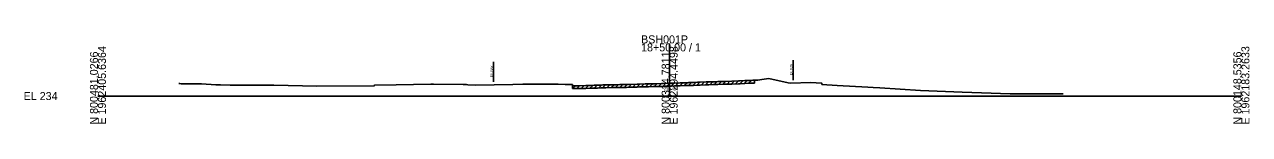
# Model space of a CAD drawing. Extents: x -26 to 1403, y -10 to 19587.
# Drawn here: x -25.7 to 402.8, y 2490.3 to 2521.3 of the extents above; entities that cross this region are included whole.
import ezdxf

# ---------------------------------------------------------------- set-up
doc = ezdxf.new("R2010")
doc.units = 0
for name, color, linetype in [('Default', 7, 'Continuous'), ('RD_GPK_XS_Cell', 7, 'Continuous'), ('RD_XS_ExGround', 7, 'Continuous'), ('RD_XS_ExPaveRet', 7, 'Continuous'), ('RD_XS_ExRW', 7, 'Continuous'), ('RD_XS_TX_Elev_EX', 7, 'Continuous')]:
    doc.layers.add(name, color=color, linetype=linetype)

msp = doc.modelspace()

# ---------------------------------------------------------------- linework, layer by layer
at = {"layer": 'RD_GPK_XS_Cell'}
for p, q in [((200, 2500), (200, 2518.45)), ((0, 2500), (200, 2500)), ((200, 2500), (400, 2500))]:
    msp.add_line(p, q, dxfattribs=at)
at = {"layer": 'RD_XS_ExGround'}
msp.add_lwpolyline([(28.28, 2504.42), (28.6, 2504.39), (29.16, 2504.33), (31.63, 2504.31), (35.81, 2504.27), (36.26, 2504.24), (41.2, 2503.94), (42.86, 2503.92), (46.31, 2503.87), (57.79, 2503.79), (61.57, 2503.8), (76.6, 2503.47), (96.63, 2503.63), (96.77, 2503.87), (104.34, 2503.95), (116.5, 2504.15), (117.42, 2504.13), (127.75, 2504), (128.97, 2504), (129.39, 2503.98), (132.03, 2503.86), (145.14, 2504.08), (148.58, 2504.14), (149.1, 2504.14), (161.04, 2504.14), (163.43, 2504.07), (165.96, 2504.04), (166.06, 2503.59), (166.34, 2503.6), (166.81, 2503.62), (167.18, 2503.63), (167.92, 2503.63), (170.62, 2503.68), (172.26, 2503.73), (173.64, 2503.77), (174.71, 2503.81), (175.87, 2503.85), (176.63, 2503.88), (177.64, 2503.91), (179.52, 2503.95), (180.37, 2503.96), (181.24, 2503.98), (182.61, 2504), (183.71, 2504.03), (184.85, 2504.05), (185.63, 2504.07), (188.63, 2504.16), (189.45, 2504.19), (191.39, 2504.25), (191.85, 2504.26), (192.63, 2504.28), (194.27, 2504.32), (194.8, 2504.33), (197.18, 2504.39), (197.69, 2504.41), (199.29, 2504.46), (200, 2504.48), (200.68, 2504.5), (201.66, 2504.53), (203.7, 2504.6), (205.12, 2504.65), (205.55, 2504.67), (206.41, 2504.69), (206.72, 2504.7), (208.3, 2504.75), (209.73, 2504.81), (210.72, 2504.85), (212.73, 2504.93), (213.71, 2504.96), (215.19, 2505.02), (215.88, 2505.04), (216.83, 2505.07), (218.72, 2505.12), (219.65, 2505.15), (221.72, 2505.22), (224.13, 2505.31), (224.72, 2505.34), (226.29, 2505.4), (227.71, 2505.46), (228.4, 2505.49), (229.04, 2505.51), (229.97, 2505.51), (230.85, 2505.62), (232.22, 2505.83), (234.75, 2506.15), (241.41, 2504.69), (242.37, 2504.57), (249.29, 2504.73), (253.18, 2504.55), (253.28, 2504.1), (258.61, 2503.73), (269.3, 2503.08), (271.21, 2502.96), (273.58, 2502.83), (287.69, 2501.97), (302.32, 2501.42), (309.09, 2501.14), (319.17, 2500.8), (337.6, 2500.73)], dxfattribs=at)
at = {"layer": 'RD_XS_ExPaveRet'}
for p, q in [((166.06, 2502.59), (167.1, 2503.63)), ((166.06, 2502.59), (166.06, 2503.59)), ((166.81, 2502.62), (167.18, 2502.63)), ((167.18, 2502.63), (167.92, 2502.63)), ((167.56, 2502.63), (168.57, 2503.64)), ((167.92, 2502.63), (170.62, 2502.68)), ((169.06, 2502.65), (170.08, 2503.67)), ((170.56, 2502.68), (171.59, 2503.71)), ((170.62, 2502.68), (172.26, 2502.73)), ((172.06, 2502.72), (173.09, 2503.75)), ((172.26, 2502.73), (173.64, 2502.77)), ((173.56, 2502.77), (174.6, 2503.8)), ((173.64, 2502.77), (174.71, 2502.81)), ((174.71, 2502.81), (175.87, 2502.85)), ((175.06, 2502.82), (176.1, 2503.86)), ((175.87, 2502.85), (176.63, 2502.88)), ((176.56, 2502.87), (177.6, 2503.91)), ((176.63, 2502.88), (177.64, 2502.91)), ((177.64, 2502.91), (179.52, 2502.95)), ((178.06, 2502.92), (179.08, 2503.94)), ((179.52, 2502.95), (180.37, 2502.96)), ((179.56, 2502.95), (180.58, 2503.96)), ((180.37, 2502.96), (181.24, 2502.98)), ((181.06, 2502.97), (182.08, 2503.99)), ((181.24, 2502.98), (182.61, 2503)), ((182.56, 2503), (183.58, 2504.02)), ((182.61, 2503), (183.71, 2503.03)), ((183.71, 2503.03), (184.85, 2503.05)), ((184.06, 2503.03), (185.08, 2504.06)), ((184.85, 2503.05), (185.63, 2503.07)), ((185.56, 2503.07), (186.59, 2504.1)), ((185.63, 2503.07), (188.63, 2503.16)), ((187.06, 2503.11), (188.09, 2504.14)), ((188.56, 2503.16), (189.6, 2504.19)), ((188.63, 2503.16), (189.45, 2503.19)), ((189.45, 2503.19), (191.39, 2503.25)), ((190.06, 2503.21), (191.1, 2504.24)), ((191.39, 2503.25), (191.85, 2503.26)), ((191.56, 2503.26), (192.58, 2504.28)), ((191.85, 2503.26), (192.63, 2503.28)), ((192.63, 2503.28), (194.27, 2503.32)), ((193.06, 2503.29), (194.09, 2504.32)), ((194.27, 2503.32), (194.8, 2503.33)), ((194.56, 2503.33), (195.59, 2504.35)), ((194.8, 2503.33), (197.18, 2503.39)), ((196.06, 2503.37), (197.09, 2504.39)), ((197.18, 2503.39), (197.69, 2503.41)), ((197.56, 2503.4), (198.59, 2504.44)), ((197.69, 2503.41), (199.29, 2503.46)), ((199.06, 2503.45), (200.09, 2504.49)), ((199.29, 2503.46), (200, 2503.48)), ((200, 2503.48), (200.68, 2503.5)), ((200.56, 2503.5), (201.59, 2504.53)), ((200.68, 2503.5), (201.66, 2503.53)), ((201.66, 2503.53), (203.7, 2503.6)), ((202.06, 2503.55), (203.09, 2504.58)), ((203.56, 2503.59), (204.6, 2504.63)), ((203.7, 2503.6), (205.12, 2503.65)), ((205.06, 2503.65), (206.1, 2504.68)), ((205.12, 2503.65), (205.55, 2503.67)), ((205.55, 2503.67), (206.41, 2503.69)), ((206.41, 2503.69), (206.72, 2503.7)), ((206.56, 2503.7), (207.59, 2504.73)), ((206.72, 2503.7), (208.3, 2503.75)), ((208.06, 2503.75), (209.1, 2504.78)), ((208.3, 2503.75), (209.73, 2503.81)), ((209.56, 2503.8), (210.6, 2504.84)), ((209.73, 2503.81), (210.72, 2503.85)), ((210.72, 2503.85), (212.73, 2503.93)), ((211.06, 2503.86), (212.1, 2504.9)), ((212.56, 2503.92), (213.6, 2504.96)), ((212.73, 2503.93), (213.71, 2503.96)), ((213.71, 2503.96), (215.19, 2504.02)), ((214.06, 2503.98), (215.1, 2505.02)), ((215.19, 2504.02), (215.88, 2504.04)), ((215.56, 2504.03), (216.59, 2505.06)), ((215.88, 2504.04), (216.83, 2504.07)), ((216.83, 2504.07), (218.72, 2504.12)), ((217.06, 2504.08), (218.09, 2505.11)), ((218.56, 2504.12), (219.59, 2505.15)), ((218.72, 2504.12), (219.65, 2504.15)), ((219.65, 2504.15), (221.72, 2504.22)), ((220.06, 2504.16), (221.09, 2505.2)), ((221.56, 2504.21), (222.6, 2505.25)), ((221.72, 2504.22), (224.13, 2504.31)), ((223.06, 2504.27), (224.1, 2505.31)), ((224.13, 2504.31), (224.72, 2504.34)), ((224.56, 2504.33), (225.6, 2505.37)), ((224.72, 2504.34), (226.29, 2504.4)), ((226.06, 2504.39), (227.11, 2505.44)), ((226.29, 2504.4), (227.71, 2504.46)), ((227.56, 2504.46), (228.6, 2505.5)), ((227.71, 2504.46), (228.4, 2504.49)), ((228.4, 2504.49), (229.04, 2504.51)), ((229.04, 2504.51), (229.73, 2504.51)), ((229.73, 2505.51), (229.73, 2504.51)), ((166.06, 2502.59), (166.34, 2502.6)), ((166.34, 2502.6), (166.81, 2502.62))]:
    msp.add_line(p, q, dxfattribs=at)
at = {"layer": 'RD_XS_ExRW'}
for p, q in [((138.32, 2504.97), (138.32, 2511.97)), ((243.15, 2505.59), (243.15, 2512.59))]:
    msp.add_line(p, q, dxfattribs=at)

# ---------------------------------------------------------------- texts
at = {"layer": 'Default'}
msp.add_text('-', height=0.0001, dxfattribs=at).set_placement((0, 2500))
at = {"layer": 'RD_GPK_XS_Cell'}
for s, p in [('BSH001P', (190, 2518.45)), ('18+50.00 / 1', (190, 2515.65)), ('EL 234', (-26, 2498.6))]:
    msp.add_text(s, height=2.8, dxfattribs=at).set_placement(p)
for s, p in [('E 1962405.6364', (2.8, 2490)), ('E 1962294.4498', (202.8, 2490)), ('E 1962183.2633', (402.8, 2490)), ('N 800481.0266', (0, 2490)), ('N 800314.7811', (200, 2490)), ('N 800148.5356', (400, 2490))]:
    msp.add_text(s, height=2.8, rotation=90, dxfattribs=at).set_placement(p)
at = {"layer": 'RD_XS_ExRW'}
for p in [(138.07, 2506.64), (242.9, 2507.26)]:
    msp.add_text('EX. R/W ', height=0.75, rotation=90, dxfattribs=at).set_placement(p)
at = {"layer": 'RD_XS_TX_Elev_EX'}
msp.add_text('238.48', height=1, dxfattribs=at).set_placement((197.95, 2501.98))

doc.saveas('drawing.dxf')
